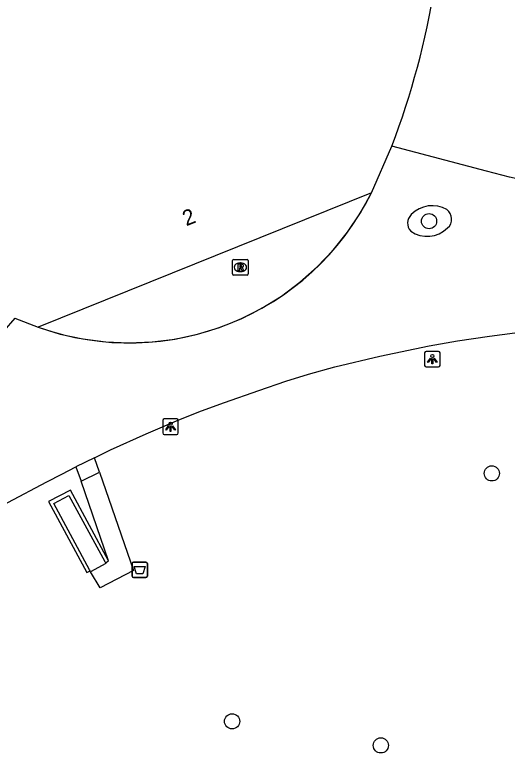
# Model space of a CAD drawing. Extents: x 161477 to 163040, y 383680 to 384868.
# Drawn here: x 161587.59 to 161619.28, y 384033.98 to 384081.8 of the extents above; entities that cross this region are included whole.
import ezdxf

# ---------------------------------------------------------------- set-up
doc = ezdxf.new("R2010")
doc.units = 0
for name, color, linetype in [('IMGEO_Afvalbak', 7, 'Continuous'), ('IMGEO_Boom', 7, 'Continuous'), ('IMGEO_Fietspad_gesloten', 7, 'Continuous'), ('IMGEO_Lichtpunt', 7, 'Continuous'), ('IMGEO_Muur', 7, 'Continuous'), ('IMGEO_Pand', 7, 'Continuous'), ('IMGEO_Pand_nummerreeks', 7, 'Continuous'), ('IMGEO_Pand_overbouw', 7, 'Continuous'), ('IMGEO_Rijbaan_lokaal_gesloten', 7, 'Continuous'), ('IMGEO_Rioolput', 7, 'Continuous'), ('IMGEO_Voetpad_gesloten', 7, 'Continuous'), ('IMGEO_Voetpad_op_trap', 7, 'Continuous'), ('IMGEO_Voetpad_open', 7, 'Continuous')]:
    doc.layers.add(name, color=color, linetype=linetype)

msp = doc.modelspace()

# ---------------------------------------------------------------- linework, layer by layer
at = {"layer": 'IMGEO_Afvalbak'}
for p, q in [((161595.235, 384046.55), (161596.025, 384046.55)), ((161596.025, 384046.55), (161595.235, 384046.55)), ((161595.135, 384045.65), (161595.135, 384046.45)), ((161595.135, 384046.45), (161595.135, 384045.65)), ((161596.125, 384046.45), (161596.125, 384045.65)), ((161596.125, 384045.65), (161596.125, 384046.45)), ((161596.025, 384045.55), (161595.235, 384045.55)), ((161595.235, 384045.55), (161596.025, 384045.55))]:
    msp.add_line(p, q, dxfattribs=at)
msp.add_lwpolyline([(161595.278, 384046.264), (161595.982, 384046.264), (161595.833, 384045.794), (161595.427, 384045.794), (161595.278, 384046.264)], dxfattribs=at)
for centre, start, end in [((161595.235, 384046.45), 90, 180), ((161595.235, 384046.45), 90, 180), ((161596.025, 384046.45), 0, 90), ((161596.025, 384046.45), 360, 90), ((161595.235, 384045.65), 180, 270), ((161595.235, 384045.65), 180, 270), ((161596.025, 384045.65), 270, 0), ((161596.025, 384045.65), 270, 0)]:
    msp.add_arc(centre, 0.1, start, end, dxfattribs=at)
at = {"layer": 'IMGEO_Boom'}
for centre in [(161614.254, 384068.507), (161618.293, 384052.264), (161601.575, 384036.292), (161611.151, 384034.742)]:
    msp.add_circle(centre, 0.489, dxfattribs=at)
at = {"layer": 'IMGEO_Fietspad_gesloten'}
msp.add_arc((161594.952, 384078.085), 17.418, 250.3499, 333.5996, dxfattribs=at)
at = {"layer": 'IMGEO_Lichtpunt'}
for p, q in [((161613.967, 384060.023), (161613.967, 384059.216)), ((161613.967, 384060.023), (161613.967, 384059.216)), ((161614.869, 384060.118), (161614.061, 384060.118)), ((161614.869, 384060.118), (161614.061, 384060.118)), ((161614.963, 384059.216), (161614.963, 384060.023)), ((161614.963, 384059.216), (161614.963, 384060.023)), ((161614.061, 384059.122), (161614.869, 384059.122)), ((161614.061, 384059.122), (161614.869, 384059.122)), ((161597.117, 384055.673), (161597.117, 384054.866)), ((161597.117, 384055.673), (161597.117, 384054.866)), ((161598.019, 384055.768), (161597.211, 384055.768)), ((161598.019, 384055.768), (161597.211, 384055.768)), ((161598.113, 384054.866), (161598.113, 384055.673)), ((161598.113, 384054.866), (161598.113, 384055.673)), ((161597.211, 384054.772), (161598.019, 384054.772)), ((161597.211, 384054.772), (161598.019, 384054.772))]:
    msp.add_line(p, q, dxfattribs=at)
for points in [[(161614.341, 384059.687), (161614.38, 384059.659), (161614.192, 384059.397), (161614.154, 384059.424), (161614.341, 384059.687)], [(161614.443, 384059.639), (161614.49, 384059.639), (161614.49, 384059.317), (161614.443, 384059.317), (161614.443, 384059.639)], [(161614.553, 384059.659), (161614.591, 384059.686), (161614.778, 384059.424), (161614.739, 384059.396), (161614.553, 384059.659)], [(161597.491, 384055.337), (161597.53, 384055.309), (161597.342, 384055.047), (161597.304, 384055.074), (161597.491, 384055.337)], [(161597.593, 384055.289), (161597.64, 384055.289), (161597.64, 384054.967), (161597.593, 384054.967), (161597.593, 384055.289)], [(161597.703, 384055.309), (161597.741, 384055.336), (161597.928, 384055.074), (161597.889, 384055.046), (161597.703, 384055.309)]]:
    msp.add_lwpolyline(points, dxfattribs=at)
for centre in [(161614.466, 384059.821), (161597.616, 384055.471)]:
    msp.add_circle(centre, 0.0994, dxfattribs=at)
for centre, start, end in [((161614.061, 384060.023), 90, 180), ((161614.061, 384060.023), 90, 180), ((161614.869, 384060.023), 0, 90), ((161614.869, 384060.023), 0, 90), ((161614.061, 384059.216), 180, 270), ((161614.061, 384059.216), 180, 270), ((161614.869, 384059.216), 270, 0), ((161614.869, 384059.216), 270, 360), ((161597.211, 384055.673), 90, 180), ((161597.211, 384055.673), 90, 180), ((161598.019, 384055.673), 0, 90), ((161598.019, 384055.673), 0, 90), ((161597.211, 384054.866), 180, 270), ((161597.211, 384054.866), 180, 270), ((161598.019, 384054.866), 270, 0), ((161598.019, 384054.866), 270, 360)]:
    msp.add_arc(centre, 0.0946, start, end, dxfattribs=at)
at = {"layer": 'IMGEO_Muur'}
for points in [[(161593.628, 384046.621), (161591.166, 384051.189), (161589.758, 384050.442), (161592.226, 384045.875), (161592.434, 384045.989)], [(161592.434, 384045.989), (161592.399, 384046.053), (161590.091, 384050.329), (161591.067, 384050.847), (161593.378, 384046.578), (161593.416, 384046.507)], [(161593.416, 384046.507), (161593.628, 384046.621)]]:
    msp.add_lwpolyline(points, dxfattribs=at)
at = {"layer": 'IMGEO_Pand'}
for points in [[(161610.554, 384070.34), (161611.855, 384073.331)], [(161610.554, 384070.34), (161589.095, 384061.681)], [(161587.591, 384062.259), (161589.095, 384061.681)]]:
    msp.add_lwpolyline(points, dxfattribs=at)
msp.add_arc((161563.415, 384091.819), 51.849, 339.1097, 350.937, dxfattribs=at)
at = {"layer": 'IMGEO_Pand_overbouw'}
msp.add_lwpolyline([(161610.554, 384070.34), (161589.095, 384061.681), (161590.517, 384061.241), (161591.971, 384060.924), (161593.447, 384060.732), (161594.933, 384060.667), (161596.42, 384060.729), (161597.897, 384060.918), (161599.351, 384061.232), (161600.774, 384061.669), (161602.154, 384062.226), (161603.482, 384062.898), (161604.747, 384063.682), (161605.941, 384064.57), (161607.054, 384065.558), (161608.08, 384066.637), (161609.009, 384067.799), (161609.836, 384069.036)], close=True, dxfattribs=at)
at = {"layer": 'IMGEO_Rijbaan_lokaal_gesloten'}
msp.add_lwpolyline([(161587.591, 384062.259), (161585.442, 384059.817), (161584.057, 384058.375), (161581.269, 384055.639), (161579.973, 384054.479), (161578.536, 384053.265), (161576.579, 384051.705), (161575.218, 384050.698), (161573.639, 384049.599), (161572.241, 384048.656), (161569.105, 384046.598), (161567.565, 384045.558), (161565.995, 384044.473), (161563.789, 384042.907), (161562.012, 384041.601), (161558.127, 384038.668), (161554.564, 384036.002), (161551.701, 384033.843)], dxfattribs=at)
at = {"layer": 'IMGEO_Rioolput'}
for p, q in [((161601.609, 384065.114), (161601.609, 384065.966)), ((161601.684, 384066.04), (161602.536, 384066.04)), ((161602.097, 384065.82), (161602.122, 384065.82)), ((161602.61, 384065.966), (161602.61, 384065.114)), ((161602.12, 384065.26), (161602.095, 384065.26)), ((161602.536, 384065.04), (161601.684, 384065.04))]:
    msp.add_line(p, q, dxfattribs=at)
for points in [[(161601.609, 384065.114), (161601.609, 384065.966)], [(161601.684, 384066.04), (161602.536, 384066.04)], [(161602.198, 384065.738), (161601.946, 384065.74), (161601.946, 384065.34)], [(161602.124, 384065.659), (161602.07, 384065.659), (161602.07, 384065.578)], [(161602.61, 384065.966), (161602.61, 384065.114)], [(161601.946, 384065.34), (161602.07, 384065.34), (161602.07, 384065.502), (161602.081, 384065.502)], [(161602.07, 384065.578), (161602.122, 384065.578)], [(161602.128, 384065.473), (161602.199, 384065.34), (161602.339, 384065.34), (161602.274, 384065.466)], [(161602.536, 384065.04), (161601.684, 384065.04)]]:
    msp.add_lwpolyline(points, dxfattribs=at)
for centre, radius, start, end in [((161601.686, 384065.964), 0.0765, 91.552, 178.448), ((161601.686, 384065.964), 0.0765, 91.552, 178.448), ((161602.13, 384065.563), 0.0964, 77.0061, 93.1865), ((161602.144, 384065.62), 0.0378, 276.6634, 79.6772), ((161602.197, 384065.628), 0.109, 350.3612, 89.416), ((161602.195, 384065.628), 0.112, 277.5842, 350.9817), ((161602.534, 384065.964), 0.0765, 1.552, 88.448), ((161602.534, 384065.964), 0.0765, 1.552, 88.448), ((161602.08, 384065.449), 0.0533, 26.0293, 88.6989), ((161602.106, 384065.767), 0.19, 274.7715, 282.9687), ((161602.179, 384065.413), 0.108, 29.5134, 73.7905), ((161601.686, 384065.116), 0.0765, 181.552, 268.448), ((161601.686, 384065.116), 0.0765, 181.552, 268.448), ((161602.534, 384065.116), 0.0765, 271.552, 358.448), ((161602.534, 384065.116), 0.0765, 271.552, 358.448)]:
    msp.add_arc(centre, radius, start, end, dxfattribs=at)
for centre, major_axis, ratio, start_param, end_param in [((161602.096, 384065.54), (-0.387, 0.002), 0.722429, 4.712389, 7.853982), ((161602.121, 384065.54), (-0.39, 0.002), 0.717154, 1.570796, 4.712389)]:
    msp.add_ellipse(centre, major_axis=major_axis, ratio=ratio, start_param=start_param, end_param=end_param, dxfattribs=at)
at = {"layer": 'IMGEO_Voetpad_gesloten'}
for points in [[(161629.256, 384070.276), (161627.968, 384070.283), (161626.195, 384070.341), (161625.235, 384070.412), (161624.228, 384070.531), (161622.616, 384070.767), (161620.128, 384071.199), (161619.424, 384071.346), (161617.96, 384071.728), (161611.855, 384073.331)], [(161592.72, 384053.274), (161593.749, 384053.774), (161596.047, 384054.816), (161596.336, 384054.942), (161598.152, 384055.712), (161599.611, 384056.29), (161601.089, 384056.836), (161603.293, 384057.612), (161605.028, 384058.197), (161606.487, 384058.661), (161608.187, 384059.136), (161611.077, 384059.816), (161614.264, 384060.475), (161616.078, 384060.791), (161618.151, 384061.1), (161619.78, 384061.327)], [(161592.72, 384053.274), (161591.527, 384052.688)], [(161543.929, 384019.716), (161544.281, 384020.031), (161547.166, 384022.454), (161550.626, 384025.277), (161554.421, 384028.279), (161558.64, 384031.533), (161565.608, 384036.738), (161569.339, 384039.44), (161572.657, 384041.719), (161575.599, 384043.633), (161578.344, 384045.35), (161581.414, 384047.202), (161583.08, 384048.154), (161587.142, 384050.391), (161589.643, 384051.721), (161590.615, 384052.22), (161591.527, 384052.688)]]:
    msp.add_lwpolyline(points, dxfattribs=at)
for centre, radius, start, end in [((161614.46, 384067.631), 1.875, 59.7268, 136.0507), ((161614.955, 384068.644), 0.755, 310.7162, 53.3677), ((161613.63, 384068.383), 0.756, 133.4171, 222.8112), ((161614.141, 384069.376), 1.846, 234.7361, 315.047)]:
    msp.add_arc(centre, radius, start, end, dxfattribs=at)
at = {"layer": 'IMGEO_Voetpad_op_trap'}
for points in [[(161593.039, 384052.347), (161592.72, 384053.274)], [(161591.527, 384052.688), (161591.849, 384051.757)], [(161592.466, 384045.93), (161592.434, 384045.989)]]:
    msp.add_lwpolyline(points, dxfattribs=at)
at = {"layer": 'IMGEO_Voetpad_open'}
for points in [[(161591.849, 384051.757), (161593.039, 384052.347)], [(161593.039, 384052.347), (161595.22, 384046.001), (161593.62, 384045.173), (161593.075, 384044.89), (161592.466, 384045.93)], [(161593.628, 384046.621), (161591.849, 384051.757)], [(161593.416, 384046.507), (161593.446, 384046.451), (161592.466, 384045.93)]]:
    msp.add_lwpolyline(points, dxfattribs=at)

# ---------------------------------------------------------------- texts
at = {"layer": 'IMGEO_Pand_nummerreeks'}
msp.add_text('2', height=1, rotation=21.738, dxfattribs=at).set_placement((161598.626, 384068.174))

doc.saveas('drawing.dxf')
